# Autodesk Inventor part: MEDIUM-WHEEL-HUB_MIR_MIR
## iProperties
Created: 2007-08
Part Number: MEDIUM-WHEEL-HUB_MIR_MIR
Material: ABS Plastic
Document SubType Name: Modeling
Mass: 42.8255 g
Surface Area: 324.402 cm^2
Volume: 40.4014 cm^3
Density: 1.06 g/cm^3
